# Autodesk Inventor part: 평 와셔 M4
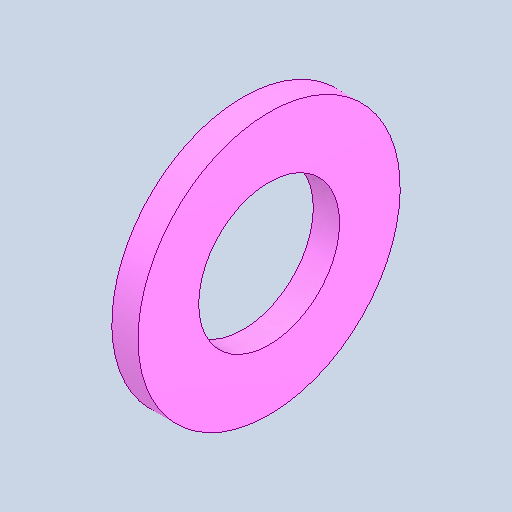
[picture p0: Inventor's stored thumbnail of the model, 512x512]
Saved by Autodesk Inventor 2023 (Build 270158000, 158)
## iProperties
Created: 2026-03
Part Number: 평 와셔 M4
Material: 강철, 연강
Description: 평면 와셔
Document SubType Name: Modeling
Designer: 4강의실
Density: 7.85 g/cm^3
Appearance: 기본값
Author: jhkim
Sending System: Autodesk Inventor 2026
Preprocessor: ST-DEVELOPER v20.1
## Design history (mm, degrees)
feature "Solid1"
node "솔리드1"
